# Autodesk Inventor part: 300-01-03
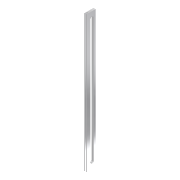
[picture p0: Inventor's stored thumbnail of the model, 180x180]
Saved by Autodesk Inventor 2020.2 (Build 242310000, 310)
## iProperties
Created: 2014-10
Part Number: 300-01-03
Material: Aluminium 6061
Document SubType Name: Modeling
Designer: F.Stasiak
Density: 2.7 g/cm^3
Appearance: Aluminium - płaski
Mass: 228.685 g
Surface Area: 498.333 cm^2
Volume: 84.6981 cm^3
Catalog Web Link: www.expertbooks.pl
Manager: www.cadconsulting.pl
Company: Fabian Stasiak CAD Consulting
Author: F.Stasiak
Subject: Zbiór ćwiczeń. Autodesk Inventor 2020. Kurs Professional
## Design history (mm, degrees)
sketch "Szkic1"
  geometry: L1 (-4, 35)-(4, 35); L2 (4, 35)-(4, 0); L3 (4, 0)-(-4, 0); L4 (-4, 0)-(-4, 35); L5 (-1.5, 8)-(1.5, 8); L6 (1.5, 8)-(1.5, 0); L7 (1.5, 0)-(-1.5, 0); L8 (-1.5, 0)-(-1.5, 8); 2 further points
  constraints: 16 end point, 4 parallel, 2 horizontal, 2 midpoint, 2 perpendicular, 1 coincident
  dimensions: "d0" = 8 distance of L2.end L3.end; "d1" = 35 distance of L1.end L2.end; "d2" = 3 distance between parallel lines of L8 L6; "d3" = 8 distance of L5.end L6.end
extrude "Wyciągnięcie proste1" new body sketch "Szkic1" stored distance "d4" = 530; taper "d5" = 0 deg
sketch "Szkic4"
  geometry: L1 (0, 8)-(0, 35); L2 (505, 21.5)-(25, 21.5); L3 (505, 28)-(25, 28); L4 (25, 15)-(505, 15); L5 (530, 35)-(0, 35) reference; A1 r 6.5 centre (505, 21.5) between (505, 15) and (505, 28); A2 r 6.5 centre (25, 21.5) between (25, 28) and (25, 15); 4 further points
  constraints: 10 end point, 4 point on circle, 4 tangent, 3 midpoint, 2 centre point, 1 horizontal, 1 horizontal alignment, 1 parallel, 1 vertical, 1 vertical alignment
  dimensions: "d11" = 480 distance of L2.start L2.end; "d12" = 13 diameter of A2
extrude "Wyciągnięcie proste3" cut sketch "Szkic4" extent not by distance; stored distance "d13" = 10; taper "d14" = 0 deg
node "Bryła1"
